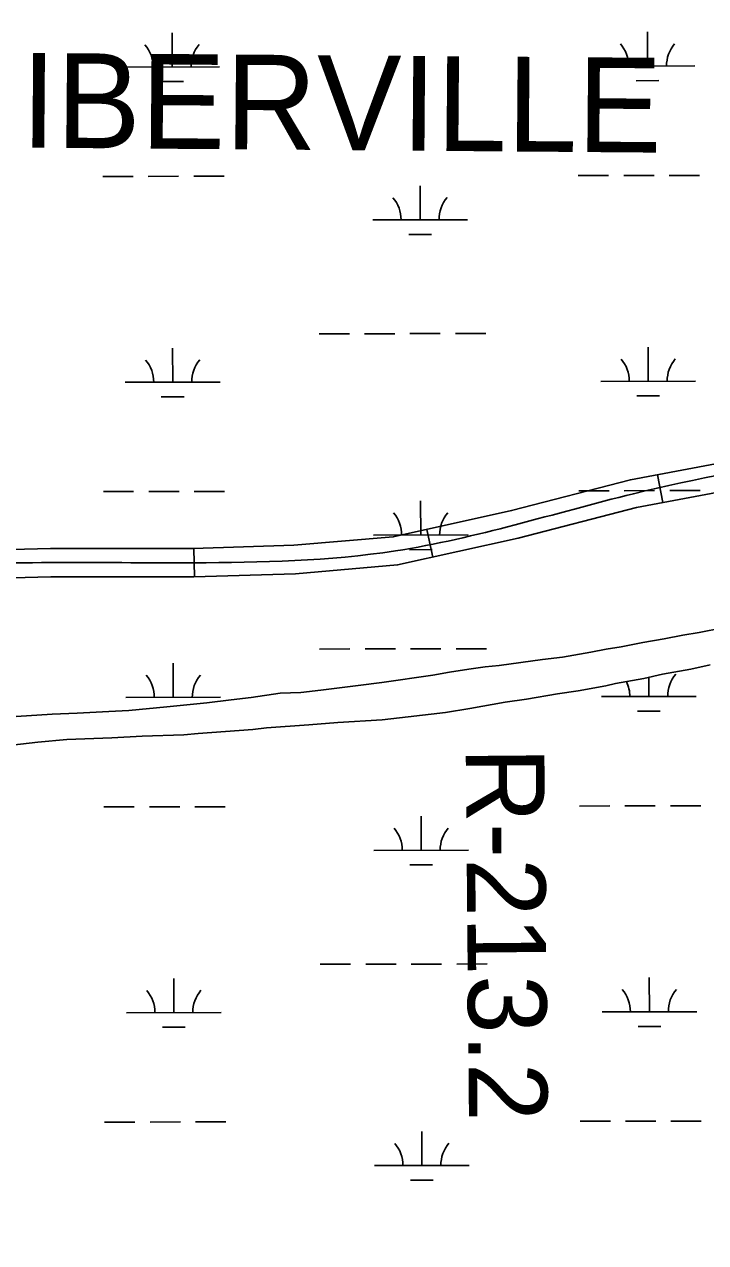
# Model space of a CAD drawing. Extents: x 3329297 to 3367176, y 649250 to 674653.
# Drawn here: x 3334498 to 3335218, y 661713 to 662998 of the extents above; entities that cross this region are included whole.
import ezdxf

# ---------------------------------------------------------------- set-up
doc = ezdxf.new("R2010")
doc.units = 0
for name, color, linetype in [('V-RIVR-EDGE', 7, 'Continuous'), ('V-RIVR-RANG-IDEN', 7, 'Continuous'), ('V-ROAD-CNTR', 7, 'Continuous'), ('V-SITE-VEGE', 7, 'Continuous'), ('V-TOPO-GNAM-IDEN', 7, 'Continuous'), ('V-WETL-SWMP', 7, 'Continuous')]:
    doc.layers.add(name, color=color, linetype=linetype)

msp = doc.modelspace()

# ---------------------------------------------------------------- linework, layer by layer
at = {"layer": 'V-RIVR-EDGE'}
msp.add_spline([(3333408.7, 669402.3), (3333456.2, 669390.7), (3333480.6, 669386.5), (3333498.4, 669381.9), (3333510.9, 669380.2), (3333522.1, 669375.2), (3333537.8, 669370.2), (3333569.3, 669364.3), (3333591.6, 669358.9), (3333623.1, 669349.7), (3333650.9, 669341.3), (3333676.1, 669333), (3333726.3, 669319.2), (3333778.9, 669302), (3333791.7, 669299.5), (3333813.6, 669293.3), (3333833.9, 669285.7), (3333853.8, 669277.4), (3333866.2, 669277.4), (3333927.5, 669258.6), (3333978.9, 669241), (3334054.7, 669220.1), (3334082, 669212.6), (3334104.4, 669205.9), (3334133.4, 669195.1), (3334212.1, 669170), (3334258.9, 669154.5), (3334287.5, 669144.9), (3334323.9, 669134.5), (3334362.8, 669121.1), (3334397.6, 669109.4), (3334435.3, 669094.8), (3334441.9, 669091.5), (3334451.9, 669089.8), (3334461, 669084), (3334464.7, 669082.7), (3334470.5, 669083.6), (3334476.3, 669080.2), (3334476.7, 669076.1), (3334486.6, 669072.7), (3334503.2, 669071.9), (3334523.5, 669067.3), (3334538.4, 669061.4), (3334550.4, 669055.2), (3334564.9, 669046.8), (3334575.7, 669042.7), (3334598.9, 669036.4), (3334626.2, 669030.9), (3334690.8, 669018.8), (3334721.1, 669015.8), (3334733.1, 669015.8), (3334745.1, 669011.2), (3334755.1, 669009.5), (3334769.6, 669008.6), (3334791.1, 669004.4), (3334799.8, 669004.4), (3334813.5, 669004.8), (3334832.6, 668999.8), (3334841.7, 668998.5), (3334844.6, 668994.8), (3334857, 668990.2), (3334864, 668983.9), (3334870.2, 668977.7), (3334876.8, 668970.2), (3334882.2, 668968.6), (3334894.6, 668965.6), (3334904.2, 668965.6), (3334918.3, 668964.3), (3334926.6, 668963.5), (3334936.1, 668958.5), (3334945.2, 668949.3), (3334956.8, 668941), (3334959.7, 668941.4), (3334971.7, 668941.4), (3334983.3, 668941.8), (3334993.2, 668938.9), (3335003.6, 668932.2), (3335011.4, 668925.1), (3335021.8, 668920.1), (3335034.2, 668916), (3335054.9, 668911.8), (3335057, 668908.9), (3335064.8, 668903.9), (3335073.5, 668900.1), (3335081, 668898), (3335087.6, 668898), (3335095.1, 668898), (3335097.6, 668895.1), (3335105, 668888.4), (3335114.1, 668882.2), (3335138.1, 668873), (3335159.7, 668864.2), (3335185.7, 668850.5), (3335195.2, 668838.9), (3335211, 668830.1), (3335229.2, 668825.5), (3335249.9, 668817.6), (3335252.4, 668811.4), (3335261.5, 668805.6), (3335272.7, 668798.5), (3335296.3, 668792.6), (3335327.3, 668778.4), (3335359.2, 668761.8), (3335399.3, 668739.7), (3335432.5, 668723.5), (3335466.4, 668708.1), (3335508.6, 668689.3), (3335535.5, 668674.3), (3335584, 668653.1), (3335614.6, 668638.1), (3335645.3, 668624.7), (3335682.1, 668600.6), (3335715.2, 668580.6), (3335752.5, 668561.5), (3335771.9, 668553.1), (3335793.9, 668548.5), (3335846.4, 668524.7), (3335870.9, 668514.7), (3335887.9, 668509.3), (3335894.9, 668501), (3335912.7, 668488.1), (3335927.6, 668478.1), (3335958.6, 668466.4), (3335986.8, 668452.7), (3336001.3, 668442.7), (3336018.7, 668434.4), (3336038.9, 668426.9), (3336117.2, 668387.3), (3336184.2, 668349), (3336223.1, 668326.5), (3336257.5, 668305.7), (3336289.4, 668284.5), (3336317.1, 668269.5), (3336332.8, 668261.6), (3336456.6, 668198.7), (3336509.2, 668170.8), (3336541.4, 668152.9), (3336585.7, 668130), (3336625.9, 668110.8), (3336652.8, 668097.9), (3336753.4, 668040), (3336798.1, 668013.8), (3336819.6, 668001.3), (3336844, 667986.8), (3336862.2, 667973.9), (3336893.7, 667952.2), (3336928, 667933.1), (3336960.3, 667914.8), (3336990.5, 667894.8), (3337029.4, 667867.8), (3337069.1, 667842.4), (3337101, 667829.5), (3337126.7, 667818.2), (3337166, 667790.3), (3337200.4, 667767.9), (3337228.5, 667747.5), (3337263.3, 667726.3), (3337288.9, 667709.2), (3337372.5, 667657.2), (3337387.8, 667642.6), (3337413.9, 667621.9), (3337448.6, 667598.6), (3337473.4, 667578.6), (3337509, 667550.7), (3337579.4, 667503.3), (3337621.1, 667469.6), (3337665, 667431), (3337708, 667391.1), (3337739.8, 667359.1), (3337772.9, 667327.1), (3337812.2, 667288.5), (3337827.1, 667271.4), (3337829.5, 667264.4), (3337842.8, 667251.5), (3337873.4, 667227.8), (3337886.2, 667214.9), (3337903.2, 667197.9), (3337949.4, 667144.7), (3337971.4, 667123.5), (3337996.2, 667096.5), (3338024.3, 667069.9), (3338047, 667044.6), (3338075.5, 667011.8), (3338104.9, 666976.9), (3338113.6, 666965.2), (3338176.8, 666889.6), (3338206.1, 666850.2), (3338224.3, 666825.3), (3338246.2, 666798.3), (3338263.5, 666774.2), (3338301.9, 666718.6), (3338311.9, 666704.5), (3338328, 666683.3), (3338335.4, 666667.9), (3338348.6, 666644.3), (3338362.6, 666627.2), (3338385.4, 666599.4), (3338404.4, 666574.5), (3338412.6, 666562), (3338414.7, 666551.3), (3338422.1, 666533), (3338443.1, 666494), (3338455.9, 666472), (3338475.4, 666449.6), (3338483.2, 666442.9), (3338498.1, 666425), (3338521.6, 666381.9), (3338562.5, 666317.5), (3338585.6, 666290.5), (3338600.5, 666260.7), (3338619.9, 666220), (3338640.9, 666179.7), (3338652.5, 666165.2), (3338660.7, 666148.6), (3338709, 666053.1), (3338735.4, 666007.5), (3338756.4, 665971.4), (3338777.1, 665937.3), (3338810.1, 665887.1), (3338828.7, 665846.4), (3338853.8, 665796.6), (3338873.6, 665751.8), (3338895.1, 665712.8), (3338903.7, 665692.1), (3338916.5, 665665.9), (3338933.8, 665635.2), (3338944.1, 665609.5), (3338956.5, 665578.8), (3338961.9, 665565.5), (3338976.7, 665543.1), (3338985, 665527.7), (3338995.3, 665511.1), (3339011.8, 665472.1), (3339026.6, 665438.9), (3339039.8, 665412.8), (3339047.6, 665382.9), (3339085.5, 665290), (3339099.5, 665253.9), (3339113.5, 665222.8), (3339126.3, 665192.5), (3339138.7, 665160.5), (3339164.2, 665092.5), (3339180.3, 665056), (3339203.7, 664990.8), (3339215.7, 664956.4), (3339231.3, 664897.5), (3339241.1, 664863.5), (3339253.9, 664825.8), (3339262.1, 664798.4), (3339275.3, 664761.9), (3339290.5, 664724.5), (3339306.2, 664692.2), (3339319, 664656.5), (3339324.3, 664636.6), (3339336.6, 664597.2), (3339352.3, 664567.7), (3339365.5, 664538.2), (3339372.1, 664519.6), (3339374.1, 664493), (3339373.2, 664478.9), (3339373.2, 664471.1), (3339377.3, 664449.9), (3339393.8, 664419.2), (3339410.3, 664384.8), (3339423.5, 664344.9), (3339458.5, 664257.4), (3339470, 664219.2), (3339470.4, 664207.2), (3339477.8, 664185.7), (3339481.1, 664164.9), (3339486.4, 664140), (3339490.1, 664124.3), (3339499.6, 664107.3), (3339512.7, 664069.9), (3339523.8, 664028.4), (3339527.5, 663998.2), (3339528.2, 663969.6), (3339525.7, 663951.8), (3339522.4, 663945.6), (3339521.1, 663939.3), (3339524, 663925.2), (3339554.1, 663875), (3339569.4, 663836), (3339574.3, 663803.7), (3339577.1, 663774.2), (3339586.9, 663730.7), (3339599.7, 663691.3), (3339610.3, 663646.9), (3339623.1, 663615.8), (3339630.5, 663595.9), (3339633.8, 663595.9), (3339643, 663599.2), (3339643, 663594.2), (3339646.2, 663566), (3339654.4, 663535.7), (3339664.3, 663503.8), (3339677, 663465.2), (3339691.9, 663427), (3339697.2, 663406.7), (3339697.2, 663392.2), (3339697.1, 663381), (3339704.9, 663354.5), (3339710.7, 663325.4), (3339723.8, 663284.4), (3339738.7, 663247.4), (3339746.1, 663222.6), (3339747.7, 663203.1), (3339746.4, 663183.6), (3339745.5, 663154.6), (3339745, 663130.5), (3339742.9, 663119.4), (3339739.6, 663107.3), (3339737, 663082.5), (3339735.3, 663062.2), (3339736.9, 663039.8), (3339742.2, 663016.6), (3339743.9, 663011.6), (3339748, 663011.6), (3339751.8, 663009.5), (3339753.8, 663002.4), (3339760, 662996.6), (3339761.2, 662990.8), (3339763.7, 662975.9), (3339763.2, 662954.8), (3339760.7, 662930.3), (3339757.8, 662927.8), (3339749.1, 662927.4), (3339743.3, 662927.4), (3339738.7, 662924.1), (3339735, 662917.9), (3339730.4, 662915.9), (3339727.5, 662912.2), (3339727.1, 662907.6), (3339732.4, 662900.1), (3339737.4, 662884.4), (3339741.9, 662869.4), (3339745.2, 662866.1), (3339748.1, 662867.3), (3339750.6, 662877.3), (3339752.7, 662878.9), (3339754.3, 662875.6), (3339755.6, 662867.7), (3339761.7, 662859), (3339764.2, 662850.7), (3339762.5, 662844.1), (3339761.7, 662822.1), (3339758.3, 662812.6), (3339756.6, 662801.8), (3339759.5, 662784), (3339757.4, 662779.4), (3339754.9, 662768.7), (3339755.3, 662757.1), (3339757.7, 662749.6), (3339761.9, 662739.6), (3339755.6, 662731), (3339746.5, 662711.1), (3339737.7, 662704.1), (3339732.8, 662703.2), (3339730.3, 662699.9), (3339733.6, 662689.6), (3339736.8, 662677.1), (3339737.2, 662668), (3339731.8, 662659.3), (3339726.4, 662644.4), (3339724.3, 662641.1), (3339729.7, 662633.2), (3339729.7, 662627.4), (3339727.2, 662625.3), (3339721.8, 662625.8), (3339721.8, 662615.4), (3339723, 662597.2), (3339722.9, 662560.7), (3339725.3, 662535.4), (3339725.3, 662520.5), (3339726.8, 662486.5), (3339724.3, 662463.3), (3339713, 662438.4), (3339703.9, 662416.9), (3339699.7, 662391.6), (3339692.9, 662333.2), (3339688.2, 662298), (3339687.4, 662274.4), (3339683.6, 662256.1), (3339676.1, 662240), (3339666.1, 662216.8), (3339659.8, 662192.8), (3339656.8, 662171.6), (3339654.7, 662126.1), (3339650.4, 662090.8), (3339644.5, 662058.5), (3339643.7, 662039.5), (3339638.2, 662015.4), (3339634.4, 661998.4), (3339628.6, 661971.9), (3339619, 661945.8), (3339616.5, 661933), (3339617.2, 661907.3), (3339619.6, 661875), (3339617.1, 661854.7), (3339612.9, 661845.6), (3339610.8, 661836.4), (3339610, 661829.8), (3339610, 661820.3), (3339609.9, 661810.7), (3339603.7, 661804.1), (3339600.8, 661799.6), (3339598.7, 661785.1), (3339594.9, 661775.6), (3339590.3, 661759.4), (3339588.6, 661741.2), (3339585.7, 661733.3), (3339580.7, 661727.5), (3339574.1, 661723.8), (3339572.8, 661715.9), (3339571.9, 661693.5), (3339564, 661655), (3339553.9, 661613.6), (3339540.6, 661574.7), (3339527.6, 661533.7), (3339508.4, 661497.2), (3339490.1, 661455.8), (3339486.8, 661446.7), (3339487.1, 661432.6), (3339486.3, 661412.3), (3339484.6, 661404), (3339476.7, 661391.6), (3339467.9, 661378.8), (3339453, 661365.1), (3339446.8, 661363.5), (3339441, 661363.1), (3339433.9, 661354.8), (3339423.5, 661346.2), (3339398.2, 661334.6), (3339381.2, 661326.8), (3339370, 661319.8), (3339357.5, 661305.3), (3339344.6, 661280), (3339333, 661269.7), (3339320.9, 661263.5), (3339313.9, 661263.1), (3339310.2, 661266), (3339308.1, 661271.8), (3339302.7, 661282.2), (3339298.6, 661286.4), (3339290.7, 661288.9), (3339284.9, 661288.9), (3339275, 661285.6), (3339261.3, 661273.2), (3339255.5, 661266.6), (3339248.8, 661265.8), (3339234.7, 661264.6), (3339224.4, 661264.2), (3339216.5, 661259.2), (3339211.9, 661252.2), (3339209.4, 661248.5), (3339211, 661240.6), (3339215.6, 661229.4), (3339215.5, 661208.2), (3339213.4, 661191.2), (3339208.8, 661185), (3339198.8, 661169.3), (3339191, 661161.9), (3339179.3, 661161.1), (3339154.5, 661165.7), (3339128, 661171.1), (3339111.4, 661176.2), (3339105.2, 661176.2), (3339096.9, 661174.1), (3339090.7, 661168.7), (3339085.7, 661157.2), (3339071.9, 661143.1), (3339054.9, 661129.9), (3339020.1, 661118.8), (3338993.5, 661110.1), (3338978.6, 661099.8), (3338965.3, 661086.2), (3338953.6, 661064.6), (3338937.4, 661039)], degree=3, dxfattribs=at)
at = {"layer": 'V-ROAD-CNTR'}
for p, q in [((3335166.8, 662523.1), (3335172.4, 662493.6)), ((3334923.1, 662465.4), (3334929.6, 662436.1)), ((3334677.2, 662445.2), (3334678.2, 662415.2))]:
    msp.add_line(p, q, dxfattribs=at)
for points in [[(3334374.6, 662441.3), (3334526, 662445.2), (3334676.7, 662445.2), (3334782.8, 662448.6), (3334887.8, 662457.5), (3335012.7, 662485.2), (3335138.1, 662517.7), (3335342, 662556.1), (3335546.4, 662590), (3335686.9, 662605.6), (3335759, 662604.1), (3335831.2, 662592.6)], [(3334376.5, 662411.3), (3334526.3, 662415.2), (3334677.2, 662415.2), (3334784.5, 662418.6), (3334892.4, 662427.8), (3335019.7, 662456.1), (3335144.6, 662488.4), (3335347.2, 662526.5), (3335550.5, 662560.3), (3335688.3, 662575.6), (3335756.3, 662574.2), (3335823, 662563.5)]]:
    msp.add_lwpolyline(points, dxfattribs=at)
msp.add_spline([(3333416.4, 662311.4), (3333590.2, 662337.9), (3333835.5, 662364.4), (3334099, 662396.8), (3334375.5, 662426.3), (3334676.9, 662430.2), (3334890.1, 662442.7), (3335141.4, 662503), (3335548.4, 662575.1), (3335827.1, 662578.1), (3335943.2, 662484.5), (3336029.1, 662325.8), (3336118.1, 662283.3), (3336195.5, 662284.9), (3336377.9, 662322.2)], degree=3, dxfattribs=at)
at = {"layer": 'V-SITE-VEGE'}
for p, q in [((3335173.7, 662349.8), (3335151.1, 662345.9)), ((3335193.4, 662353.6), (3335173.7, 662349.8)), ((3335210.9, 662356.7), (3335193.4, 662353.6)), ((3335235.6, 662361.4), (3335210.9, 662356.7)), ((3335112.5, 662339), (3335096.5, 662335.9)), ((3335128.5, 662341.3), (3335112.5, 662339)), ((3335151.1, 662345.9), (3335128.5, 662341.3)), ((3335045.5, 662328.1), (3334999.5, 662321.8)), ((3335066.6, 662330.5), (3335045.5, 662328.1)), ((3335096.5, 662335.9), (3335066.6, 662330.5)), ((3334929.6, 662311.6), (3334875.6, 662303.8)), ((3334947.1, 662314.7), (3334929.6, 662311.6)), ((3334967.5, 662317.8), (3334947.1, 662314.7)), ((3334985, 662320.2), (3334967.5, 662317.8)), ((3334999.5, 662321.8), (3334985, 662320.2)), ((3335152.2, 662308), (3335171.9, 662312.6)), ((3335171.9, 662312.6), (3335201.8, 662318)), ((3335201.8, 662318), (3335222.2, 662322.5)), ((3334850.9, 662300.6), (3334811.5, 662295.8)), ((3334875.6, 662303.8), (3334850.9, 662300.6)), ((3335083, 662294.9), (3335112.2, 662300.3)), ((3335112.2, 662300.3), (3335122.4, 662302.6)), ((3335122.4, 662302.6), (3335152.2, 662308)), ((3334716.7, 662285.4), (3334691.2, 662282.2)), ((3334737.9, 662287.8), (3334716.7, 662285.4)), ((3334768.5, 662292.5), (3334737.9, 662287.8)), ((3334790.4, 662293.4), (3334768.5, 662292.5)), ((3334811.5, 662295.8), (3334790.4, 662293.4)), ((3335005.8, 662283.2), (3335028.4, 662286.3)), ((3335028.4, 662286.3), (3335061.2, 662291.7)), ((3335061.2, 662291.7), (3335083, 662294.9)), ((3334587.6, 662273.2), (3334554.1, 662271.4)), ((3334608.8, 662274.1), (3334587.6, 662273.2)), ((3334648.9, 662278.1), (3334608.8, 662274.1)), ((3334691.2, 662282.2), (3334648.9, 662278.1)), ((3334943.1, 662272.3), (3334968.6, 662276.2)), ((3334968.6, 662276.2), (3335005.8, 662283.2)), ((3334527.8, 662270.4), (3334489.9, 662267.8)), ((3334554.1, 662271.4), (3334527.8, 662270.4)), ((3334798.7, 662259.2), (3334829.4, 662261.7)), ((3334829.4, 662261.7), (3334876, 662264.4)), ((3334876, 662264.4), (3334903.7, 662267.5)), ((3334903.7, 662267.5), (3334943.1, 662272.3)), ((3334590.8, 662245.5), (3334622.9, 662247.2)), ((3334622.9, 662247.2), (3334666.7, 662248.4)), ((3334666.7, 662248.4), (3334682, 662250)), ((3334682, 662250), (3334739.6, 662254.2)), ((3334739.6, 662254.2), (3334754.2, 662255.8)), ((3334754.2, 662255.8), (3334798.7, 662259.2)), ((3334472.7, 662236.2), (3334512.8, 662241)), ((3334512.8, 662241), (3334543.4, 662243.5)), ((3334543.4, 662243.5), (3334590.8, 662245.5))]:
    msp.add_line(p, q, dxfattribs=at)
at = {"layer": 'V-WETL-SWMP'}
for p, q in [((3334654.4, 662953.4), (3334654.3, 662989.4)), ((3335156.3, 662954.4), (3335156.2, 662990.4)), ((3335106.3, 662954.3), (3335206.3, 662954.5)), ((3334604.4, 662953.3), (3334704.4, 662953.5)), ((3334642.4, 662938), (3334666.4, 662938)), ((3335144.3, 662938.9), (3335168.3, 662939)), ((3335083.1, 662838.8), (3335115.1, 662838.9)), ((3335131.1, 662838.9), (3335163.1, 662838.9)), ((3335179.1, 662839), (3335211.1, 662839)), ((3334581.2, 662837.8), (3334613.2, 662837.9)), ((3334629.2, 662837.9), (3334661.2, 662838)), ((3334677.2, 662838), (3334709.2, 662838.1)), ((3334916.1, 662792), (3334916.1, 662828)), ((3334866.1, 662791.9), (3334966.1, 662792.1)), ((3334904.2, 662776.6), (3334928.2, 662776.6)), ((3334809.5, 662671.8), (3334841.5, 662671.8)), ((3334857.5, 662671.9), (3334889.5, 662671.9)), ((3334905.5, 662672), (3334937.5, 662672)), ((3334953.5, 662672), (3334985.5, 662672.1)), ((3334655, 662620.7), (3334654.9, 662656.7)), ((3335156.9, 662621.7), (3335156.8, 662657.7)), ((3334605, 662620.6), (3334705, 662620.8)), ((3335106.9, 662621.6), (3335206.9, 662621.8)), ((3334643, 662605.3), (3334667, 662605.3)), ((3335144.9, 662606.2), (3335168.9, 662606.3)), ((3334581.8, 662505.2), (3334613.8, 662505.2)), ((3334629.8, 662505.3), (3334661.8, 662505.3)), ((3334677.8, 662505.3), (3334709.8, 662505.4)), ((3335083.7, 662506.1), (3335115.7, 662506.2)), ((3335131.7, 662506.2), (3335163.7, 662506.3)), ((3335179.7, 662506.3), (3335211.7, 662506.4)), ((3334916.8, 662459.4), (3334916.7, 662495.4)), ((3334866.8, 662459.3), (3334966.8, 662459.5)), ((3334904.8, 662443.9), (3334928.8, 662444)), ((3335173.7, 662349.8), (3335151.1, 662345.9)), ((3335193.4, 662353.6), (3335173.7, 662349.8)), ((3335210.9, 662356.7), (3335193.4, 662353.6)), ((3335235.6, 662361.4), (3335210.9, 662356.7)), ((3334810.1, 662339.1), (3334842.1, 662339.2)), ((3334858.1, 662339.2), (3334890.1, 662339.2)), ((3334906.1, 662339.3), (3334938.1, 662339.3)), ((3334954.1, 662339.4), (3334986.1, 662339.4)), ((3335112.5, 662339), (3335096.5, 662335.9)), ((3335128.5, 662341.3), (3335112.5, 662339)), ((3335151.1, 662345.9), (3335128.5, 662341.3)), ((3334655.6, 662288.1), (3334655.6, 662324.1)), ((3335045.5, 662328.1), (3334999.5, 662321.8)), ((3335066.6, 662330.5), (3335045.5, 662328.1)), ((3335096.5, 662335.9), (3335066.6, 662330.5)), ((3334929.6, 662311.6), (3334875.6, 662303.8)), ((3334947.1, 662314.7), (3334929.6, 662311.6)), ((3334967.5, 662317.8), (3334947.1, 662314.7)), ((3334985, 662320.2), (3334967.5, 662317.8)), ((3334999.5, 662321.8), (3334985, 662320.2)), ((3335152.2, 662308), (3335171.9, 662312.6)), ((3335171.9, 662312.6), (3335201.8, 662318)), ((3335201.8, 662318), (3335222.2, 662322.5)), ((3334850.9, 662300.6), (3334811.5, 662295.8)), ((3334875.6, 662303.8), (3334850.9, 662300.6)), ((3335083, 662294.9), (3335112.2, 662300.3)), ((3335112.2, 662300.3), (3335122.4, 662302.6)), ((3335122.4, 662302.6), (3335152.2, 662308)), ((3335157.5, 662289), (3335157.5, 662309.2)), ((3334605.6, 662288), (3334705.6, 662288.2)), ((3334716.7, 662285.4), (3334691.2, 662282.2)), ((3334737.9, 662287.8), (3334716.7, 662285.4)), ((3334768.5, 662292.5), (3334737.9, 662287.8)), ((3334790.4, 662293.4), (3334768.5, 662292.5)), ((3334811.5, 662295.8), (3334790.4, 662293.4)), ((3335005.8, 662283.2), (3335028.4, 662286.3)), ((3335028.4, 662286.3), (3335061.2, 662291.7)), ((3335061.2, 662291.7), (3335083, 662294.9)), ((3335107.5, 662288.9), (3335207.5, 662289.1)), ((3334587.6, 662273.2), (3334554.1, 662271.4)), ((3334608.8, 662274.1), (3334587.6, 662273.2)), ((3334648.9, 662278.1), (3334608.8, 662274.1)), ((3334691.2, 662282.2), (3334648.9, 662278.1)), ((3334943.1, 662272.3), (3334968.6, 662276.2)), ((3334968.6, 662276.2), (3335005.8, 662283.2)), ((3335145.6, 662273.6), (3335169.6, 662273.6)), ((3334527.8, 662270.4), (3334489.9, 662267.8)), ((3334554.1, 662271.4), (3334527.8, 662270.4)), ((3334798.7, 662259.2), (3334829.4, 662261.7)), ((3334829.4, 662261.7), (3334876, 662264.4)), ((3334876, 662264.4), (3334903.7, 662267.5)), ((3334903.7, 662267.5), (3334943.1, 662272.3)), ((3334590.8, 662245.5), (3334622.9, 662247.2)), ((3334622.9, 662247.2), (3334666.7, 662248.4)), ((3334666.7, 662248.4), (3334682, 662250)), ((3334682, 662250), (3334739.6, 662254.2)), ((3334739.6, 662254.2), (3334754.2, 662255.8)), ((3334754.2, 662255.8), (3334798.7, 662259.2)), ((3334472.7, 662236.2), (3334512.8, 662241)), ((3334512.8, 662241), (3334543.4, 662243.5)), ((3334543.4, 662243.5), (3334590.8, 662245.5)), ((3334582.4, 662172.5), (3334614.4, 662172.6)), ((3334630.4, 662172.6), (3334662.4, 662172.6)), ((3334678.4, 662172.7), (3334710.4, 662172.7)), ((3335084.4, 662173.4), (3335116.4, 662173.5)), ((3335132.4, 662173.5), (3335164.4, 662173.6)), ((3335180.4, 662173.6), (3335212.4, 662173.7)), ((3334917.4, 662126.7), (3334917.3, 662162.7)), ((3334867.4, 662126.6), (3334967.4, 662126.8)), ((3334905.4, 662111.2), (3334929.4, 662111.3)), ((3334810.8, 662006.4), (3334842.8, 662006.5)), ((3334858.8, 662006.5), (3334890.8, 662006.6)), ((3334906.8, 662006.6), (3334938.8, 662006.7)), ((3334954.8, 662006.7), (3334986.8, 662006.8)), ((3334656.3, 661955.4), (3334656.2, 661991.4)), ((3335158.2, 661956.3), (3335158.1, 661992.3)), ((3334606.3, 661955.3), (3334706.3, 661955.5)), ((3335108.2, 661956.2), (3335208.2, 661956.4)), ((3334644.3, 661939.9), (3334668.3, 661940)), ((3335146.2, 661940.9), (3335170.2, 661940.9)), ((3334583.1, 661839.8), (3334615.1, 661839.9)), ((3334631.1, 661839.9), (3334663.1, 661840)), ((3334679.1, 661840), (3334711.1, 661840.1)), ((3335085, 661840.8), (3335117, 661840.8)), ((3335133, 661840.9), (3335165, 661840.9)), ((3335181, 661840.9), (3335213, 661841)), ((3334918, 661794), (3334917.9, 661830)), ((3334868, 661793.9), (3334968, 661794.1)), ((3334906, 661778.6), (3334930, 661778.6))]:
    msp.add_line(p, q, dxfattribs=at)
for centre, start, end in [((3334599.1, 662953.8), 359.3365, 40.8801), ((3334709.6, 662954), 139.3365, 180.8801), ((3335101, 662954.7), 359.3365, 40.8801), ((3335211.5, 662954.9), 139.3365, 180.8801), ((3334860.9, 662792.4), 359.3365, 40.8801), ((3334971.4, 662792.6), 139.3365, 180.8801), ((3334599.8, 662621.1), 359.3365, 40.8801), ((3334710.3, 662621.3), 139.3365, 180.8801), ((3335101.7, 662622.1), 359.3365, 40.8801), ((3335212.2, 662622.3), 139.3365, 180.8801), ((3334861.5, 662459.7), 359.3365, 40.8801), ((3334972, 662459.9), 139.3365, 180.8801), ((3334600.4, 662288.4), 359.3365, 40.8801), ((3334710.9, 662288.6), 139.3365, 180.8801), ((3335212.8, 662289.6), 139.3365, 180.8801), ((3335102.3, 662289.4), 359.3365, 25.7385), ((3334862.1, 662127.1), 359.3365, 40.8801), ((3334972.6, 662127.3), 139.3365, 180.8801), ((3334601, 661955.8), 359.3365, 40.8801), ((3334711.5, 661956), 139.3365, 180.8801), ((3335102.9, 661956.7), 359.3365, 40.8801), ((3335213.4, 661956.9), 139.3365, 180.8801), ((3334862.8, 661794.4), 359.3365, 40.8801), ((3334973.3, 661794.6), 139.3365, 180.8801)]:
    msp.add_arc(centre, 35.2, start, end, dxfattribs=at)

# ---------------------------------------------------------------- texts
at = {"layer": 'V-RIVR-RANG-IDEN'}
msp.add_text('R-213.2', height=83, rotation=270.5026, dxfattribs=at).set_placement((3334964.3, 662235.3))
at = {"layer": 'V-TOPO-GNAM-IDEN'}
msp.add_text('IBERVILLE', height=100, rotation=359.5486, dxfattribs=at).set_placement((3334494.6, 662868.3))

doc.saveas('drawing.dxf')
